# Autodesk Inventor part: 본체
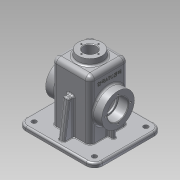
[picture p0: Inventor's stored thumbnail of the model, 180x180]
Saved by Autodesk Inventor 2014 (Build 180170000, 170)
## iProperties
Created: 2016-08
Part Number: 본체
Material: 알루미늄 6061
Document SubType Name: Modeling
Designer: user
Density: 2.71 g/cm^3
Appearance: 알루미늄 - 평지
Mass: 800.3 g
Surface Area: 911.822 cm^2
Volume: 295.314 cm^3
Author: user
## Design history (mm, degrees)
sketch "스케치2"
  geometry: L1 (-51, -52.5)-(51, -52.5); L2 (60, -43.5)-(60, 43.5); L3 (51, 52.5)-(-51, 52.5); L4 (-60, 43.5)-(-60, -43.5); L5 (-60, -52.5)-(60, 52.5); L6 (60, -52.5)-(-60, 52.5); A1 r 9 centre (-51, 43.5) between (-51, 52.5) and (-60, 43.5); A2 r 9 centre (51, 43.5) between (60, 43.5) and (51, 52.5); A3 r 9 centre (-51, -43.5) between (-60, -43.5) and (-51, -52.5); A4 r 9 centre (51, -43.5) between (51, -52.5) and (60, -43.5); 1 further point
  constraints: 12 end point, 8 point on circle, 8 point on line, 8 tangent, 4 centre point, 3 equal radius, 2 midpoint, 2 parallel, 1 horizontal, 1 perpendicular
  dimensions: "d0" = 120 distance of L6.end L5.end; "d1" = 105 distance of L5.end L6.start; "d2" = 9 radius of A1
extrude "돌출1" new body sketch "스케치2" distance "d3" = 3; taper "d4" = 0 deg
sketch "스케치3"
  geometry: L1 (-51, -57.5)-(51, -57.5); L2 (65, -43.5)-(65, 43.5); L3 (51, 57.5)-(-51, 57.5); L4 (-65, 43.5)-(-65, -43.5); L5 (-65, -57.5)-(65, 57.5); L6 (65, -57.5)-(-65, 57.5); A1 r 14 centre (-51, 43.5) between (-51, 57.5) and (-65, 43.5); A2 r 14 centre (51, 43.5) between (65, 43.5) and (51, 57.5); A3 r 14 centre (-51, -43.5) between (-65, -43.5) and (-51, -57.5); A4 r 14 centre (51, -43.5) between (51, -57.5) and (65, -43.5); 1 further point
  constraints: 12 end point, 8 point on circle, 8 point on line, 8 tangent, 4 centre point, 3 equal radius, 2 midpoint, 2 parallel, 1 horizontal, 1 perpendicular
  dimensions: "d5" = 130 distance of L6.end L5.end; "d6" = 115 distance of L5.end L6.start; "d7" = 14 radius of A1
extrude "돌출2" join sketch "스케치3" distance "d8" = 7; taper "d9" = 0 deg
sketch "스케치4"
  geometry: L1 (32.5, 0)-(-32.5, 0); L2 (-32.5, 0)-(-32.5, 110); L3 (-32.5, 110)-(32.5, 110); L4 (32.5, 110)-(32.5, 0); L5 (51, 0)-(-51, 0) reference; L6 (71.4, 0)-(-71.4, 0) reference; L7 (0, -22)-(0, 132) reference; 1 further point
  constraints: 8 end point, 2 parallel, 1 collinear, 1 horizontal, 1 perpendicular, 1 other
  dimensions: "d10" = 65 distance of L2.end L3.end; "d11" = 110 distance of L1.end L2.end
extrude "돌출3" join sketch "스케치4" stored distance "d12" = 65; taper "d13" = 0 deg
fillet "모깎기1" dims "d14" = 8
sketch "스케치5"
  geometry: L1 (47.5, 82.5)-(-47.5, 82.5); L2 (-47.5, 82.5)-(-47.5, 55); L3 (-47.5, 55)-(47.5, 55); L4 (47.5, 55)-(47.5, 82.5); L5 (66.5, 0)-(-66.5, 0) reference; L6 (0, -20.4)-(0, 122.4) reference; 1 further point
  constraints: 8 end point, 2 parallel, 1 horizontal, 1 perpendicular, 1 other
  dimensions: "d15" = 27.5 distance of L3.end L1.start; "d16" = 95 distance of L1.start L1.end; "d17" = 55 distance between parallel lines of L5 L3
revolve "회전1" sketch "스케치5" stored, may be unused: angle "d18" = 90 deg
fillet "모깎기5" dims "d83" = 3
sketch "스케치6"
  geometry: L1 (24.5, 110)-(-24.5, 110) reference; L2 (0, 110)-(0, 120); L3 (0, 120)-(-20, 120); L4 (-20, 120)-(-21.228, 110); L5 (0, 110)-(-21.228, 110); L6 (-32.5, 102)-(-32.5, 67.49) reference; 1 further point
  constraints: 8 end point, 2 perpendicular, 1 midpoint, 1 parallel, 1 point on line
  dimensions: "d19" = 7 deg angle of L6 L4; "d20" = 40 diameter of L3.end L2; "d21" = 10 distance of L2.start L2.end
revolve "회전2" sketch "스케치6" stored, may be unused: angle "d22" = 90 deg
sketch "스케치7"
  geometry: L1 (-32.5, 10)-(-32.5, 102) reference; L2 (43.5, 10)-(-43.5, 10) reference; L3 (-43.5, 10)-(-57.5, 10) reference; L4 (-32.5, 70)-(-41.068, 70); L5 (-41.068, 70)-(-49.5, 10); L6 (-57.5, 3)-(-57.5, 10) reference; L7 (-52.5, 0)-(-43.5, 0) reference; 1 further point
  constraints: 4 end point, 2 point on line, 1 parallel
  dimensions: "d23" = 8 deg angle of L6 L5; "d24" = 70 distance from line of L7 L4.end; "d25" = 8 distance of L3.end L5.end
extrude "돌출4" join sketch "스케치7" stored distance "d26" = 10; taper "d27" = 0 deg
sketch "스케치8"
  geometry: L1 (-42.5, 10)-(42.5, 10); L2 (32.5, 27.5)-(47.5, 27.5) reference; L3 (-47.5, 27.5)-(-32.5, 27.5) reference; L4 (-51, 10)-(51, 10) reference; L5 (32.5, 10)-(32.5, 42.51) reference; L6 (-32.5, 42.51)-(-32.5, 10) reference; L7 (42.5, 10)-(42.5, 55); L8 (42.5, 55)-(-42.5, 55); L9 (-42.5, 55)-(-42.5, 10); L10 (47.5, 27.5)-(47.5, 82.5) reference; 2 further points
  constraints: 8 end point, 2 perpendicular, 1 collinear, 1 midpoint, 1 parallel, 1 point on line
  dimensions: "d84" = 10 distance between parallel lines of L7 L5; "d85" = 10 distance between parallel lines of L9 L6
extrude "돌출5" join sketch "스케치8" stored distance "d30" = 6; taper "d31" = 0 deg
node "작업 평면1"
sketch "스케치9"
  geometry: L1 (0, -8)-(92, -8) reference; L2 (-18, 44.5)-(-18, 4.5) reference; 2 further points
  constraints: 1 other
  dimensions: "d33" = 32.5 distance from line of L1 point (8, 24.5); "d34" = 26 distance from line of point (8, 24.5) L2
feature "엠보싱1" sketch "스케치9" dims "d5" = 130, "d6" = 115, "d7" = 14, "d35" = 0.5, "d36" = 0
sketch "스케치10"
  geometry: L1 (55, -80.5)-(55, 80.5) reference; L2 (77, 0)-(-77, 0) reference; L3 (0, -21)-(0, 21); C1 r 27.5 at (0, 0) reference; A1 r 21 centre (0, 0) between (0, -21) and (0, 21); 5 further points
  constraints: 4 point on circle, 2 coincident, 2 end point, 2 midpoint, 2 point on line, 1 centre point, 1 concentric, 1 perpendicular
  dimensions: "d37" = 42 diameter of A1
hole "구멍1" sketch "스케치10" at (-21, 0), (0, -21), (21, 0), (0, 21) diameter "d38" = 3.242; stored, may be unused: countersink angle "d42" = 90 deg, drill point angle "d44" = 118 deg; dims "d39" = 8, "d40" = 4, "d41" = 2, "d43" = 10
sketch "스케치11"
  geometry: L1 (-91, 0)-(91, 0) reference; L2 (0, -80.5)-(0, 80.5) reference; A1 r 14.5 centre (0, 0) between (0, 14.5) and (0, -14.5); 3 further points
  constraints: 4 point on circle, 4 point on line, 1 centre point, 1 coincident
  dimensions: "d45" = 29 diameter of A1
hole "구멍2" sketch "스케치11" at (0, 14.5), (0, -14.5), (-14.5, 0), (14.5, 0) diameter "d46" = 2.459; stored, may be unused: countersink angle "d50" = 90 deg, drill point angle "d52" = 118 deg; dims "d47" = 7, "d48" = 4, "d49" = 2, "d51" = 9
sketch "스케치12"
  geometry: L1 (47.5, 27.5)-(47.5, 82.5) reference; L2 (-47.5, 27.5)-(-47.5, 82.5) reference; L3 (47.5, 55)-(-47.5, 55); L4 (47.5, 55)-(47.5, 72.5); L5 (47.5, 72.5)-(30.5, 72.5); L6 (30.5, 72.5)-(30.5, 70); L7 (30.5, 70)-(-30.5, 70); L8 (-30.5, 70)-(-30.5, 72.5); L9 (-30.5, 72.5)-(-47.5, 72.5); L10 (-47.5, 55)-(-47.5, 72.5); 1 further point
  constraints: 16 end point, 3 perpendicular, 2 midpoint, 2 parallel, 2 point on line, 1 collinear
  dimensions: "d53" = 35 diameter of L5 L3; "d54" = 35 diameter of L9 L3; "d55" = 30 diameter of L7 L3; "d56" = 17 distance of L4.end L5.end; "d57" = 17 distance of L8.end L9.end
revolve "회전3" sketch "스케치12" stored, may be unused: angle "d58" = 90 deg
sketch "스케치13"
  geometry: L1 (51, 0)-(-51, 0) reference; L2 (27.5, 105)-(-27.5, 105); L3 (-27.5, 105)-(-27.5, 0); L4 (-27.5, 0)-(27.5, 0); L5 (27.5, 0)-(27.5, 105); L6 (27.5, 105)-(-27.5, 0); L7 (-27.5, 105)-(27.5, 0); L8 (91, 0)-(-91, 0) reference; L9 (0, -24)-(0, 144) reference; L10 (-32.5, 102)-(-32.5, 67.49) reference; L11 (24.5, 110)-(-24.5, 110) reference; 3 further points
  constraints: 12 end point, 3 midpoint, 2 parallel, 1 collinear, 1 horizontal, 1 perpendicular, 1 point on line
  dimensions: "d59" = 5 distance between parallel lines of L10 L3; "d60" = 5 distance between parallel lines of L11 L2
extrude "돌출6" cut sketch "스케치13" stored distance "d61" = 55; taper "d62" = 0 deg
fillet "모깎기2" dims "d63" = 3
chamfer "모따기1" distance "d64" = 1; stored, may be unused: second distance "d65" = 2, angle "d66" = 45 deg
fillet "모깎기3" dims "d67" = 0.3
hole "구멍3" diameter "d70" = 21; stored, may be unused: countersink angle "d74" = 90 deg, drill point angle "d76" = 118 deg; dims "d71" = 21, "d72" = 4, "d73" = 2, "d75" = 9, "d77" = 10, "d78" = 10
chamfer "모따기2" distance "d79" = 1; stored, may be unused: second distance "d80" = 2, angle "d81" = 45 deg
fillet "모깎기4" dims "d82" = 3
fillet "모깎기9" dims "d89" = 3
sketch "스케치14"
  geometry: L1 (91, 0)-(-91, 0) reference; L2 (0, -80.5)-(0, 80.5) reference; 5 further points
  constraints: 2 horizontal alignment, 2 symmetric about line, 2 vertical alignment
  dimensions: "d93" = 87 distance of point (-51, 43.5) point (-51, -43.5); "d94" = 102 distance of point (51, 43.5) point (-51, 43.5)
hole "구멍4" sketch "스케치14" at (-51, -43.5), (-51, 43.5), (51, 43.5), (51, -43.5) diameter "d95" = 8; stored, may be unused: countersink angle "d99" = 90 deg, drill point angle "d101" = 118 deg; dims "d96" = 21, "d97" = 4, "d98" = 2, "d100" = 9
fillet "모깎기13" dims "d102" = 3
fillet "모깎기15" dims "d104" = 3
fillet "모깎기16" dims "d105" = 3
fillet "모깎기17" dims "d106" = 3
fillet "모깎기18" dims "d107" = 3
fillet "모깎기19" dims "d108" = 3
fillet "모깎기20" dims "d109" = 1
node "솔리드1"
mirror "대칭1"
mirror "대칭2"
node "투영된 루프1"
other parameters: "d32" = 29
